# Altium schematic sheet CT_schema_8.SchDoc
size 277 x 170 mm
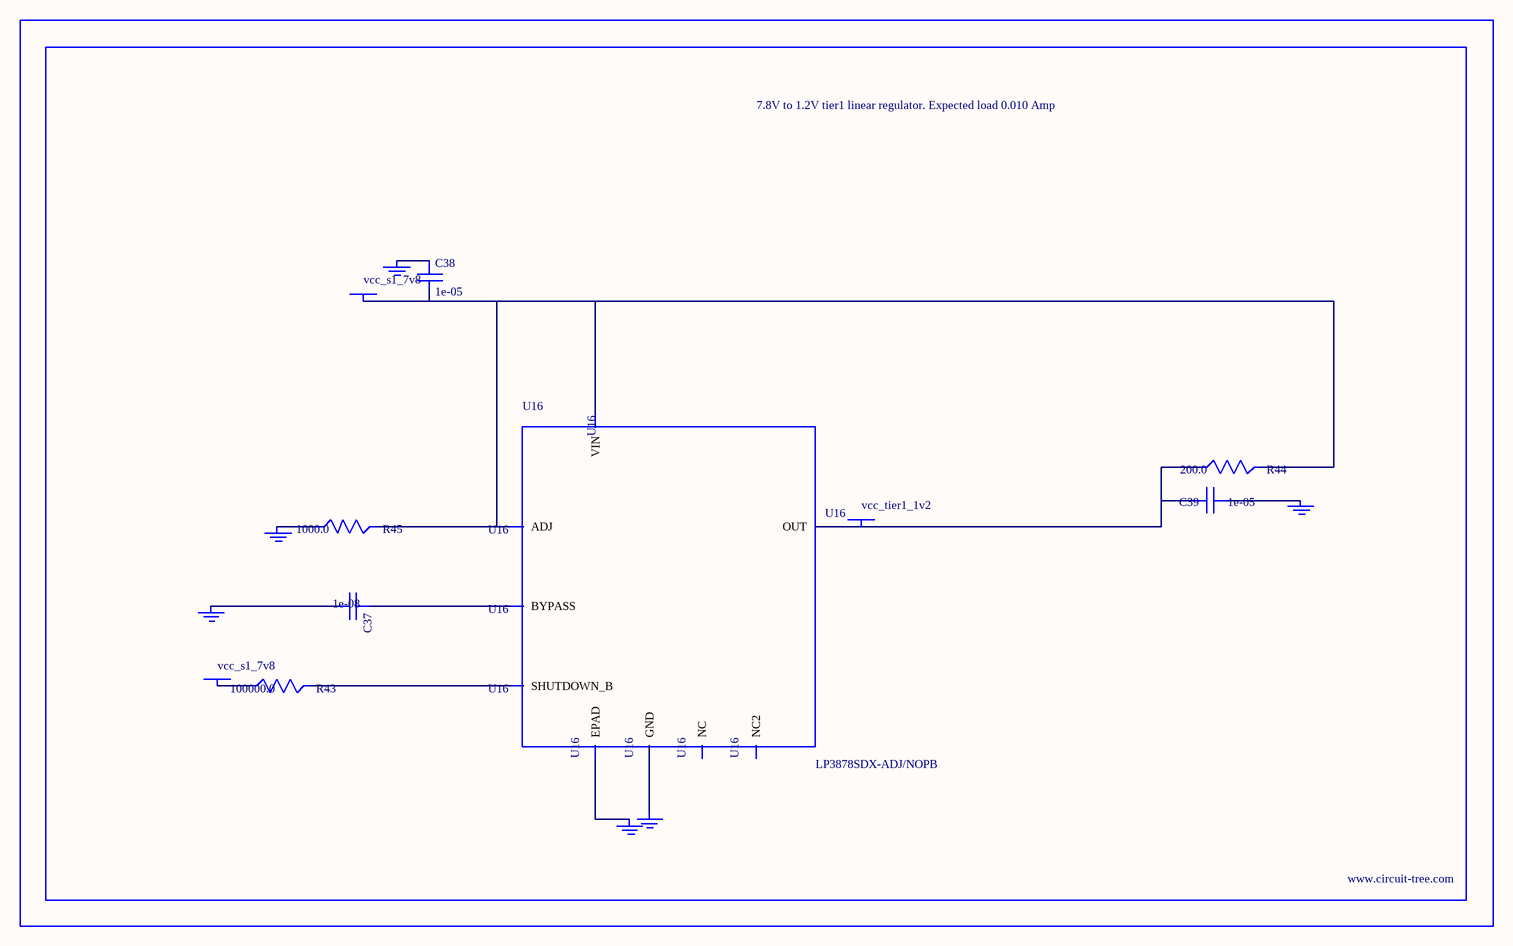
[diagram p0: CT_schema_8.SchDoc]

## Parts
BORDER7  (no value)
C37  1e-08  [C0402]
C38  1e-05  [C1206]
C39  1e-05  [C0805]
GND_INSTANCE_7_0  (no value)
GND_INSTANCE_7_1  (no value)
GND_INSTANCE_7_2  (no value)
GND_INSTANCE_7_3  (no value)
GND_INSTANCE_7_4  (no value)
GND_INSTANCE_7_5  (no value)
POWER_INSTANCE_7_0  vcc_s1_7v8
POWER_INSTANCE_7_1  vcc_s1_7v8
POWER_INSTANCE_7_2  vcc_tier1_1v2
R43  100000.0  [R0603]
R44  200.0  [R0603]
R45  1000.0  [R0603]
U16  LP3878SDX-ADJ/NOPB  [WSON-8]

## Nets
NetC37_1: C37.1 U16.1(BYPASS)
NetC37_2: C37.2 GND_INSTANCE_7_0.0(GND)
NetC38_1: C38.1 GND_INSTANCE_7_1.0(GND)
NetC38_2: C38.2 POWER_INSTANCE_7_0.0(PWR) R44.2 R45.2 U16.4(VIN) U16.6(ADJ)
NetC39_1: C39.1 GND_INSTANCE_7_2.0(GND)
NetC39_2: C39.2 POWER_INSTANCE_7_2.0(PWR) R44.1 U16.5(OUT)
NetGND_INSTANCE_7_3_0: GND_INSTANCE_7_3.0(GND) R45.1
NetGND_INSTANCE_7_4_0: GND_INSTANCE_7_4.0(GND) U16.PAD(EPAD)
NetGND_INSTANCE_7_5_0: GND_INSTANCE_7_5.0(GND) U16.3(GND)
NetPOWER_INSTANCE_7_1_0: POWER_INSTANCE_7_1.0(PWR) R43.1
NetR43_2: R43.2 U16.8(SHUTDOWN_B)

Not connected (* = marked no-connect by the designer): U16 2(NC) 7(NC2)

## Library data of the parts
BORDER7 = BORDER_PAGE7
C37 = C0402C103K3RAC
C38 = C1206C106K3RACTU
C39 = GRM219R60J106ME19D
GND_INSTANCE_7_0-GND_INSTANCE_7_5 = GND
POWER_INSTANCE_7_0-POWER_INSTANCE_7_2 = PWR
R43 = RC0603JR-07100KL
R44 = RC0603JR-07200RL
R45 = RC0603JR-071KL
